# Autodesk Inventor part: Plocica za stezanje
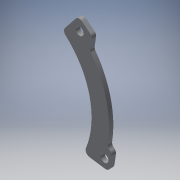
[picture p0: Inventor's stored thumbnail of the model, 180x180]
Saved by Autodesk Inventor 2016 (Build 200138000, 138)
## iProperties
Created: 2015-08
Part Number: Plocica za stezanje
Material: Generic
Document SubType Name: Modeling
Designer: Ugljesa
Density: 1 g/cm^3
Appearance: Default
Author: Ugljesa
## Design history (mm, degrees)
sketch "Sketch1"
  geometry: L1 (33.06, -94.151)-(33.855, -94.787); L2 (35.674, -99.444)-(33.848, -111.419); L3 (28.152, -115.609)-(9.919, -112.829); L4 (-18.132, 1.784)-(-5.554, 17.502); L5 (1.474, 18.282)-(10.932, 10.714); L6 (12.751, 6.056)-(11.133, -4.556); L7 (-77.405, -72.288)-(10.135, 37.108); C1 r 4.5 at (-1.155, 6.995) reference; C2 r 4.5 at (27.495, -105.393); C3 r 4.5 at (27.495, -105.393) reference; A1 r 90 centre (-77.405, -72.288) between (6.037, -106.013) and (-17.553, -5.074); A2 r 110 centre (-77.405, -72.288) between (31.245, -89.466) and (12.012, -8.221); A3 r 5 centre (7.808, 6.81) between (12.751, 6.056) and (10.932, 10.714); A4 r 5 centre (16.076, -5.309) between (11.133, -4.556) and (12.012, -8.221); A5 r 5 centre (36.184, -90.247) between (31.245, -89.466) and (33.06, -94.151); A6 r 5 centre (30.731, -98.691) between (35.674, -99.444) and (33.855, -94.787); A7 r 5 centre (28.905, -110.666) between (28.152, -115.609) and (33.848, -111.419); A8 r 5 centre (10.673, -107.887) between (6.037, -106.013) and (9.919, -112.829); A9 r 5 centre (-14.228, -1.34) between (-18.132, 1.784) and (-17.553, -5.074); A10 r 5 centre (-1.65, 14.378) between (1.474, 18.282) and (-5.554, 17.502); 9 further points
  constraints: 26 point on circle, 16 tangent, 14 end point, 12 centre point, 12 point on line, 7 equal radius, 2 coincident, 2 perpendicular, 1 collinear, 2 other
  dimensions: "d1" = 110 radius of A2; "d2" = 90 radius of A1; "d4" = 60 deg angle of L4 L3; "d5" = 30 distance of point (33.095, -116.362) point (3.437, -111.841); "d8" = 30 distance of point (-21.174, -2.017) point (-2.43, 21.406); "d9" = 10 distance from line of L4 C1.centre; "d10" = 10 distance from line of L3 C2.centre; "d11" = 20 distance of point (36.109, -96.591) point (33.095, -116.362); "d12" = 20 distance of point (-2.43, 21.406) point (13.186, 8.91); "d13" = 30 deg angle of L3 L1; "d14" = 30 deg angle of L7 L6; "d15" = 5 radius of A3; "d19" = 9 diameter of C2
extrude "Extrusion1" new body sketch "Sketch1" distance "d16" = 3; taper "d17" = 0 deg
body "Solid1"
node "Reference1"
